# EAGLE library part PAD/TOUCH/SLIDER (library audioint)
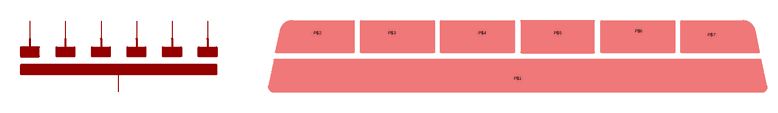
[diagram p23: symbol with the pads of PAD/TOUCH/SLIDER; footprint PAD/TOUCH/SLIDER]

Designator prefix -

## PAD/TOUCH/SLIDERSLIDER  [PAD/TOUCH/SLIDER]
P$1  P$1
P$2  P$2
P$3  P$3
P$4  P$4
P$5  P$5
P$6  P$6
P$7  P$7

## Footprint PAD/TOUCH/SLIDER (pad centres in mm)
smd 1.27 x 0.635: P$1 0,-3.048; P$2 -27.305,3.175; P$3 -17.145,3.175; P$4 -4.826,3.175; P$5 5.461,3.175; P$6 16.51,3.429; P$7 26.416,2.921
